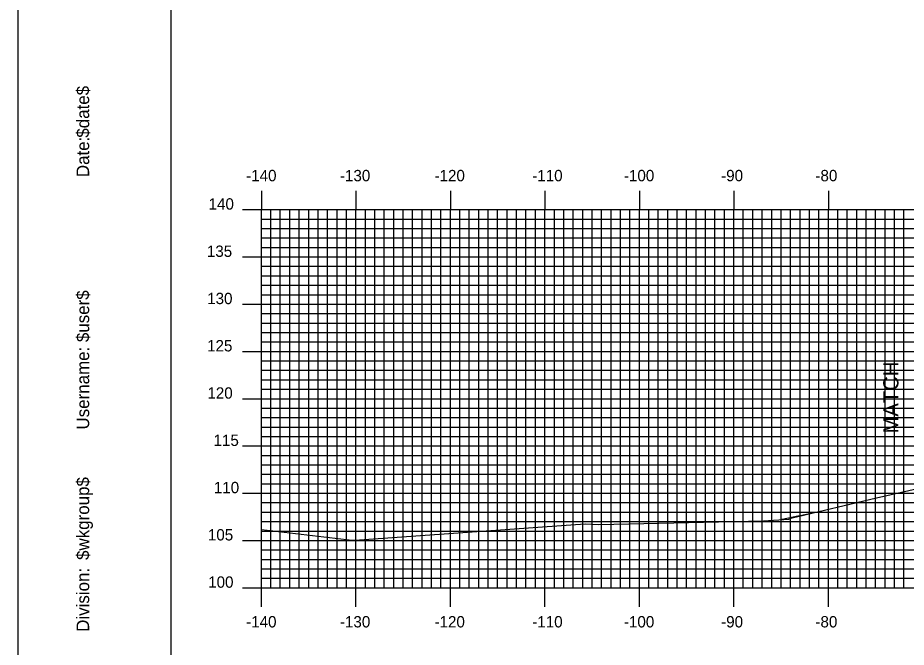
# Model space of a CAD drawing. Extents: x 1685192 to 1685536, y 461260 to 461480.
# Drawn here: x 1685192.4 to 1685286.5, y 461346.8 to 461413.4 of the extents above; entities that cross this region are included whole.
import ezdxf

# ---------------------------------------------------------------- set-up
doc = ezdxf.new("R2010")
doc.units = 0
for name, color, linetype in [('ANNOTATION', 7, 'Continuous'), ('BORDER', 7, 'Continuous'), ('H_V ANNOTATION', 7, 'Continuous'), ('MAJOR', 7, 'Continuous'), ('MINOR', 7, 'Continuous'), ('PLOT BOUNDARY', 7, 'Continuous'), ('S_Roadway_Centerline', 7, 'Continuous')]:
    doc.layers.add(name, color=color, linetype=linetype)

msp = doc.modelspace()

# ---------------------------------------------------------------- linework, layer by layer
at = {"layer": 'BORDER'}
msp.add_lwpolyline([(1685208.629, 461266.072), (1685528.629, 461266.072), (1685528.629, 461476.072), (1685208.629, 461476.072)], close=True, dxfattribs=at)
at = {"layer": 'MAJOR'}
for p, q in [((1685218.229, 461395.076), (1685218.229, 461393.072)), ((1685228.229, 461395.076), (1685228.229, 461393.072)), ((1685238.229, 461395.076), (1685238.229, 461393.072)), ((1685248.229, 461395.076), (1685248.229, 461393.072)), ((1685258.229, 461395.076), (1685258.229, 461393.072)), ((1685268.229, 461395.076), (1685268.229, 461393.072)), ((1685278.229, 461395.076), (1685278.229, 461393.072)), ((1685216.225, 461393.072), (1685218.229, 461393.072)), ((1685218.229, 461393.072), (1685498.229, 461393.072)), ((1685218.229, 461353.072), (1685218.229, 461393.072)), ((1685218.229, 461353.072), (1685218.229, 461393.072)), ((1685218.229, 461393.072), (1685498.229, 461393.072)), ((1685228.229, 461353.072), (1685228.229, 461393.072)), ((1685238.229, 461353.072), (1685238.229, 461393.072)), ((1685248.229, 461353.072), (1685248.229, 461393.072)), ((1685258.229, 461353.072), (1685258.229, 461393.072)), ((1685268.229, 461353.072), (1685268.229, 461393.072)), ((1685278.229, 461353.072), (1685278.229, 461393.072)), ((1685216.225, 461388.072), (1685218.229, 461388.072)), ((1685218.229, 461388.072), (1685498.229, 461388.072)), ((1685216.225, 461383.072), (1685218.229, 461383.072)), ((1685218.229, 461383.072), (1685498.229, 461383.072)), ((1685216.225, 461378.072), (1685218.229, 461378.072)), ((1685218.229, 461378.072), (1685498.229, 461378.072)), ((1685216.225, 461373.072), (1685218.229, 461373.072)), ((1685218.229, 461373.072), (1685498.229, 461373.072)), ((1685216.225, 461368.072), (1685218.229, 461368.072)), ((1685218.229, 461368.072), (1685498.229, 461368.072)), ((1685216.225, 461363.072), (1685218.229, 461363.072)), ((1685218.229, 461363.072), (1685498.229, 461363.072)), ((1685216.225, 461358.072), (1685218.229, 461358.072)), ((1685218.229, 461358.072), (1685498.229, 461358.072)), ((1685216.225, 461353.072), (1685218.229, 461353.072)), ((1685218.229, 461353.072), (1685498.229, 461353.072)), ((1685218.229, 461353.072), (1685498.229, 461353.072)), ((1685218.229, 461351.068), (1685218.229, 461353.072)), ((1685228.229, 461351.068), (1685228.229, 461353.072)), ((1685238.229, 461351.068), (1685238.229, 461353.072)), ((1685248.229, 461351.068), (1685248.229, 461353.072)), ((1685258.229, 461351.068), (1685258.229, 461353.072)), ((1685268.229, 461351.068), (1685268.229, 461353.072)), ((1685278.229, 461351.068), (1685278.229, 461353.072))]:
    msp.add_line(p, q, dxfattribs=at)
at = {"layer": 'MINOR'}
for p, q in [((1685219.229, 461353.072), (1685219.229, 461393.072)), ((1685220.229, 461353.072), (1685220.229, 461393.072)), ((1685221.229, 461353.072), (1685221.229, 461393.072)), ((1685222.229, 461353.072), (1685222.229, 461393.072)), ((1685223.229, 461353.072), (1685223.229, 461393.072)), ((1685224.229, 461353.072), (1685224.229, 461393.072)), ((1685225.229, 461353.072), (1685225.229, 461393.072)), ((1685226.229, 461353.072), (1685226.229, 461393.072)), ((1685227.229, 461353.072), (1685227.229, 461393.072)), ((1685229.229, 461353.072), (1685229.229, 461393.072)), ((1685230.229, 461353.072), (1685230.229, 461393.072)), ((1685231.229, 461353.072), (1685231.229, 461393.072)), ((1685232.229, 461353.072), (1685232.229, 461393.072)), ((1685233.229, 461353.072), (1685233.229, 461393.072)), ((1685234.229, 461353.072), (1685234.229, 461393.072)), ((1685235.229, 461353.072), (1685235.229, 461393.072)), ((1685236.229, 461353.072), (1685236.229, 461393.072)), ((1685237.229, 461353.072), (1685237.229, 461393.072)), ((1685239.229, 461353.072), (1685239.229, 461393.072)), ((1685240.229, 461353.072), (1685240.229, 461393.072)), ((1685241.229, 461353.072), (1685241.229, 461393.072)), ((1685242.229, 461353.072), (1685242.229, 461393.072)), ((1685243.229, 461353.072), (1685243.229, 461393.072)), ((1685244.229, 461353.072), (1685244.229, 461393.072)), ((1685245.229, 461353.072), (1685245.229, 461393.072)), ((1685246.229, 461353.072), (1685246.229, 461393.072)), ((1685247.229, 461353.072), (1685247.229, 461393.072)), ((1685249.229, 461353.072), (1685249.229, 461393.072)), ((1685250.229, 461353.072), (1685250.229, 461393.072)), ((1685251.229, 461353.072), (1685251.229, 461393.072)), ((1685252.229, 461353.072), (1685252.229, 461393.072)), ((1685253.229, 461353.072), (1685253.229, 461393.072)), ((1685254.229, 461353.072), (1685254.229, 461393.072)), ((1685255.229, 461353.072), (1685255.229, 461393.072)), ((1685256.229, 461353.072), (1685256.229, 461393.072)), ((1685257.229, 461353.072), (1685257.229, 461393.072)), ((1685259.229, 461353.072), (1685259.229, 461393.072)), ((1685260.229, 461353.072), (1685260.229, 461393.072)), ((1685261.229, 461353.072), (1685261.229, 461393.072)), ((1685262.229, 461353.072), (1685262.229, 461393.072)), ((1685263.229, 461353.072), (1685263.229, 461393.072)), ((1685264.229, 461353.072), (1685264.229, 461393.072)), ((1685265.229, 461353.072), (1685265.229, 461393.072)), ((1685266.229, 461353.072), (1685266.229, 461393.072)), ((1685267.229, 461353.072), (1685267.229, 461393.072)), ((1685269.229, 461353.072), (1685269.229, 461393.072)), ((1685270.229, 461353.072), (1685270.229, 461393.072)), ((1685271.229, 461353.072), (1685271.229, 461393.072)), ((1685272.229, 461353.072), (1685272.229, 461393.072)), ((1685273.229, 461353.072), (1685273.229, 461393.072)), ((1685274.229, 461353.072), (1685274.229, 461393.072)), ((1685275.229, 461353.072), (1685275.229, 461393.072)), ((1685276.229, 461353.072), (1685276.229, 461393.072)), ((1685277.229, 461353.072), (1685277.229, 461393.072)), ((1685279.229, 461353.072), (1685279.229, 461393.072)), ((1685280.229, 461353.072), (1685280.229, 461393.072)), ((1685281.229, 461353.072), (1685281.229, 461393.072)), ((1685282.229, 461353.072), (1685282.229, 461393.072)), ((1685283.229, 461353.072), (1685283.229, 461393.072)), ((1685284.229, 461353.072), (1685284.229, 461393.072)), ((1685285.229, 461353.072), (1685285.229, 461393.072)), ((1685286.229, 461353.072), (1685286.229, 461393.072)), ((1685218.229, 461392.072), (1685498.229, 461392.072)), ((1685218.229, 461392.072), (1685220.233, 461392.072)), ((1685218.229, 461391.072), (1685498.229, 461391.072)), ((1685218.229, 461391.072), (1685220.233, 461391.072)), ((1685218.229, 461390.072), (1685498.229, 461390.072)), ((1685218.229, 461390.072), (1685220.233, 461390.072)), ((1685218.229, 461389.072), (1685498.229, 461389.072)), ((1685218.229, 461389.072), (1685220.233, 461389.072)), ((1685218.229, 461387.072), (1685498.229, 461387.072)), ((1685218.229, 461387.072), (1685220.233, 461387.072)), ((1685218.229, 461386.072), (1685498.229, 461386.072)), ((1685218.229, 461386.072), (1685220.233, 461386.072)), ((1685218.229, 461385.072), (1685498.229, 461385.072)), ((1685218.229, 461385.072), (1685220.233, 461385.072)), ((1685218.229, 461384.072), (1685498.229, 461384.072)), ((1685218.229, 461384.072), (1685220.233, 461384.072)), ((1685218.229, 461382.072), (1685498.229, 461382.072)), ((1685218.229, 461382.072), (1685220.233, 461382.072)), ((1685218.229, 461381.072), (1685498.229, 461381.072)), ((1685218.229, 461381.072), (1685220.233, 461381.072)), ((1685218.229, 461380.072), (1685498.229, 461380.072)), ((1685218.229, 461380.072), (1685220.233, 461380.072)), ((1685218.229, 461379.072), (1685498.229, 461379.072)), ((1685218.229, 461379.072), (1685220.233, 461379.072)), ((1685218.229, 461377.072), (1685498.229, 461377.072)), ((1685218.229, 461377.072), (1685220.233, 461377.072)), ((1685218.229, 461376.072), (1685498.229, 461376.072)), ((1685218.229, 461376.072), (1685220.233, 461376.072)), ((1685218.229, 461375.072), (1685498.229, 461375.072)), ((1685218.229, 461375.072), (1685220.233, 461375.072)), ((1685218.229, 461374.072), (1685498.229, 461374.072)), ((1685218.229, 461374.072), (1685220.233, 461374.072)), ((1685218.229, 461372.072), (1685498.229, 461372.072)), ((1685218.229, 461372.072), (1685220.233, 461372.072)), ((1685218.229, 461371.072), (1685498.229, 461371.072)), ((1685218.229, 461371.072), (1685220.233, 461371.072)), ((1685218.229, 461370.072), (1685498.229, 461370.072)), ((1685218.229, 461370.072), (1685220.233, 461370.072)), ((1685218.229, 461369.072), (1685498.229, 461369.072)), ((1685218.229, 461369.072), (1685220.233, 461369.072)), ((1685218.229, 461367.072), (1685498.229, 461367.072)), ((1685218.229, 461367.072), (1685220.233, 461367.072)), ((1685218.229, 461366.072), (1685498.229, 461366.072)), ((1685218.229, 461366.072), (1685220.233, 461366.072)), ((1685218.229, 461365.072), (1685498.229, 461365.072)), ((1685218.229, 461365.072), (1685220.233, 461365.072)), ((1685218.229, 461364.072), (1685498.229, 461364.072)), ((1685218.229, 461364.072), (1685220.233, 461364.072)), ((1685218.229, 461362.072), (1685498.229, 461362.072)), ((1685218.229, 461362.072), (1685220.233, 461362.072)), ((1685218.229, 461361.072), (1685498.229, 461361.072)), ((1685218.229, 461361.072), (1685220.233, 461361.072)), ((1685218.229, 461360.072), (1685498.229, 461360.072)), ((1685218.229, 461360.072), (1685220.233, 461360.072)), ((1685218.229, 461359.072), (1685498.229, 461359.072)), ((1685218.229, 461359.072), (1685220.233, 461359.072)), ((1685218.229, 461357.072), (1685498.229, 461357.072)), ((1685218.229, 461357.072), (1685220.233, 461357.072)), ((1685218.229, 461356.072), (1685498.229, 461356.072)), ((1685218.229, 461356.072), (1685220.233, 461356.072)), ((1685218.229, 461355.072), (1685498.229, 461355.072)), ((1685218.229, 461355.072), (1685220.233, 461355.072)), ((1685218.229, 461354.072), (1685498.229, 461354.072)), ((1685218.229, 461354.072), (1685220.233, 461354.072))]:
    msp.add_line(p, q, dxfattribs=at)
at = {"layer": 'PLOT BOUNDARY'}
msp.add_lwpolyline([(1685192.443, 461259.954), (1685532.443, 461259.954), (1685532.443, 461479.954), (1685192.443, 461479.954)], close=True, dxfattribs=at)
at = {"layer": 'S_Roadway_Centerline'}
for points in [[(1685218.229, 461359.221), (1685227.817, 461358.112), (1685228.098, 461358.114), (1685251.485, 461359.769), (1685252.544, 461359.829), (1685253.954, 461359.76), (1685271.35, 461360.14), (1685274.054, 461360.321), (1685274.399, 461360.457), (1685283.329, 461362.585), (1685290.941, 461364.299)], [(1685272.989, 461360.25), (1685273.245, 461360.307), (1685273.334, 461360.327), (1685275.002, 461360.678), (1685275.231, 461360.726), (1685276.912, 461361.056)]]:
    msp.add_lwpolyline(points, dxfattribs=at)

# ---------------------------------------------------------------- texts
at = {"layer": 'ANNOTATION'}
msp.add_text('MATCH', height=1.6, rotation=90, dxfattribs=at).set_placement((1685285.642, 461369.389))
at = {"layer": 'BORDER'}
for s, p in [('$date$', (1685199.999, 461400.682)), ('Date:', (1685199.999, 461396.506)), ('$user$', (1685199.999, 461379.055)), ('Username:', (1685199.999, 461369.808)), ('$wkgroup$', (1685199.999, 461356.011)), ('Division:', (1685199.999, 461348.404))]:
    msp.add_text(s, height=1.3392, rotation=90, dxfattribs=at).set_placement(p)
at = {"layer": 'H_V ANNOTATION'}
for s, p in [('-140', (1685216.613, 461396.072)), ('-130', (1685226.538, 461396.072)), ('-120', (1685236.549, 461396.072)), ('-110', (1685246.892, 461396.072)), ('-100', (1685256.592, 461396.072)), ('-90', (1685266.881, 461396.072)), ('-80', (1685276.859, 461396.072)), ('140', (1685212.639, 461393.072)), ('135', (1685212.457, 461388.072)), ('130', (1685212.489, 461383.072)), ('125', (1685212.478, 461378.072)), ('120', (1685212.51, 461373.072)), ('115', (1685213.164, 461368.072)), ('110', (1685213.196, 461363.072)), ('105', (1685212.564, 461358.072)), ('100', (1685212.596, 461353.072)), ('-140', (1685216.613, 461348.872)), ('-130', (1685226.538, 461348.872)), ('-120', (1685236.549, 461348.872)), ('-110', (1685246.892, 461348.872)), ('-100', (1685256.592, 461348.872)), ('-90', (1685266.881, 461348.872)), ('-80', (1685276.859, 461348.872))]:
    msp.add_text(s, height=1.2, dxfattribs=at).set_placement(p)
at = {"layer": 'MAJOR'}
msp.add_text('-', height=0.012, dxfattribs=at).set_placement((1685218.22, 461353.072))

doc.saveas('drawing.dxf')
